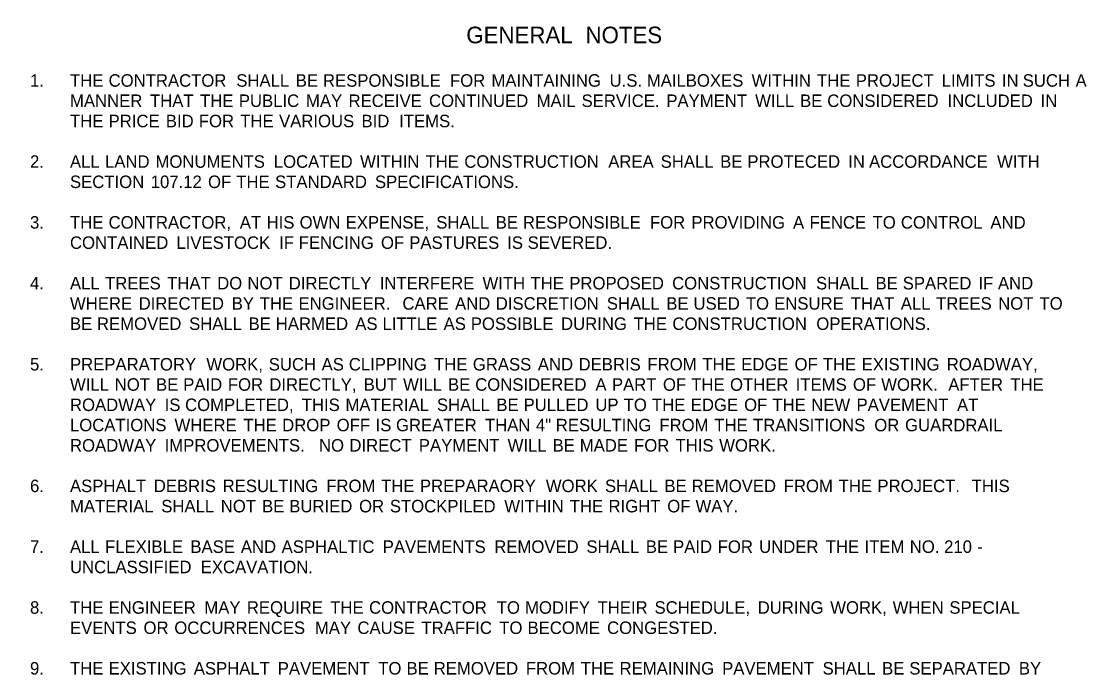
# Model space of a CAD drawing. Extents: x 1930579 to 1932218, y 596452 to 599480.
# Drawn here: x 1930760 to 1931323, y 599048 to 599394 of the extents above; entities that cross this region are included whole.
import ezdxf

# ---------------------------------------------------------------- set-up
doc = ezdxf.new("R2010")
doc.units = 0
doc.layers.add('Default', color=7, linetype='Continuous')
doc.layers.add('R_Border', color=7, linetype='Continuous')

msp = doc.modelspace()

# ---------------------------------------------------------------- linework, layer by layer
at = {"layer": 'R_Border'}
msp.add_line((1930759.59, 599393.53), (1930759.59, 599393.53), dxfattribs=at)

# ---------------------------------------------------------------- texts
at = {"layer": 'Default'}
for s, height, p in [('GENERAL', 8.8, (1930994.83, 599381.89)), (' NOTES', 8.8, (1931054.58, 599381.89)), ('1.', 6.6, (1930764.2, 599358.92)), ('THE', 6.6, (1930785.33, 599358.92)), (' CONTRACTOR', 6.6, (1930803.29, 599358.92)), (' SHALL', 6.6, (1930870.79, 599358.92)), (' BE', 6.6, (1930902.24, 599358.92)), (' RESPONSIBLE', 6.6, (1930916.61, 599358.92)), (' FOR', 6.6, (1930983.78, 599358.92)), (' MAINTAINING', 6.6, (1931005.68, 599358.92)), (' U.S.', 6.6, (1931068.12, 599358.92)), (' MAILBOXES', 6.6, (1931087.81, 599358.92)), (' WITHIN', 6.6, (1931143.19, 599358.92)), (' THE', 6.6, (1931177.77, 599358.92)), (' PROJECT', 6.6, (1931198.29, 599358.92)), (' LIMITS', 6.6, (1931243.71, 599358.92)), (' IN', 6.6, (1931275.5, 599358.92)), (' SUCH', 6.6, (1931286.53, 599358.92)), (' A', 6.6, (1931314.47, 599358.92)), ('MANNER', 6.6, (1930785.33, 599348.2)), (' THAT', 6.6, (1930825.17, 599348.2)), (' THE', 6.6, (1930851.63, 599348.2)), (' PUBLIC', 6.6, (1930872.14, 599348.2)), (' MAY', 6.6, (1930907.65, 599348.2)), (' RECEIVE', 6.6, (1930930.13, 599348.2)), (' CONTINUED', 6.6, (1930972.68, 599348.2)), (' MAIL', 6.6, (1931029.57, 599348.2)), (' SERVICE.', 6.6, (1931053.33, 599348.2)), (' PAYMENT', 6.6, (1931098.13, 599348.2)), (' WILL', 6.6, (1931145.09, 599348.2)), (' BE', 6.6, (1931168.84, 599348.2)), (' CONSIDERED', 6.6, (1931183.21, 599348.2)), (' INCLUDED', 6.6, (1931246.77, 599348.2)), (' IN', 6.6, (1931295.98, 599348.2)), ('THE', 6.6, (1930785.33, 599337.47)), (' PRICE', 6.6, (1930803.29, 599337.47)), (' BID', 6.6, (1930833.54, 599337.47)), (' FOR', 6.6, (1930850.98, 599337.47)), (' THE', 6.6, (1930872.88, 599337.47)), (' VARIOUS', 6.6, (1930893.4, 599337.47)), (' BID', 6.6, (1930936.99, 599337.47)), ('  ITEMS.', 6.6, (1930954.43, 599337.47)), ('2.', 6.6, (1930764.2, 599316.02)), ('ALL', 6.6, (1930785.33, 599316.02)), (' LAND', 6.6, (1930801.41, 599316.02)), (' MONUMENTS', 6.6, (1930828.08, 599316.02)), (' LOCATED', 6.6, (1930890.61, 599316.02)), (' WITHIN', 6.6, (1930936.24, 599316.02)), (' THE', 6.6, (1930970.82, 599316.02)), (' CONSTRUCTION', 6.6, (1930991.34, 599316.02)), (' AREA', 6.6, (1931067.43, 599316.02)), (' SHALL', 6.6, (1931095.13, 599316.02)), (' BE', 6.6, (1931126.58, 599316.02)), (' PROTECED', 6.6, (1931140.95, 599316.02)), (' IN', 6.6, (1931194.26, 599316.02)), (' ACCORDANCE', 6.6, (1931205.29, 599316.02)), (' WITH', 6.6, (1931272.95, 599316.02)), ('SECTION', 6.6, (1930785.33, 599305.3)), (' 107.12', 6.6, (1930825.57, 599305.3)), (' OF', 6.6, (1930855.84, 599305.3)), (' THE', 6.6, (1930870.78, 599305.3)), (' STANDARD', 6.6, (1930891.3, 599305.3)), (' SPECIFICATIONS.', 6.6, (1930944.1, 599305.3)), ('3.', 6.6, (1930764.2, 599283.85)), ('THE', 6.6, (1930785.33, 599283.85)), (' CONTRACTOR,', 6.6, (1930803.29, 599283.85)), (' AT', 6.6, (1930872.66, 599283.85)), (' HIS', 6.6, (1930886.82, 599283.85)), (' OWN', 6.6, (1930904.27, 599283.85)), (' EXPENSE,', 6.6, (1930928.61, 599283.85)), (' SHALL', 6.6, (1930976.49, 599283.85)), (' BE', 6.6, (1931007.94, 599283.85)), (' RESPONSIBLE', 6.6, (1931022.31, 599283.85)), (' FOR', 6.6, (1931089.47, 599283.85)), (' PROVIDING', 6.6, (1931111.37, 599283.85)), (' A', 6.6, (1931165.11, 599283.85)), (' FENCE', 6.6, (1931173.84, 599283.85)), (' TO', 6.6, (1931207.16, 599283.85)), (' CONTROL', 6.6, (1931222.12, 599283.85)), (' AND', 6.6, (1931269.44, 599283.85)), ('CONTAINED', 6.6, (1930785.33, 599273.12)), (' LIVESTOCK', 6.6, (1930839.15, 599273.12)), (' IF', 6.6, (1930893.46, 599273.12)), (' FENCING', 6.6, (1930903.79, 599273.12)), (' OF', 6.6, (1930947.27, 599273.12)), (' PASTURES', 6.6, (1930962.22, 599273.12)), (' IS', 6.6, (1931014.01, 599273.12)), (' SEVERED.', 6.6, (1931024.8, 599273.12)), ('4.', 6.6, (1930764.2, 599251.67)), ('ALL', 6.6, (1930785.33, 599251.67)), (' TREES', 6.6, (1930801.41, 599251.67)), (' THAT', 6.6, (1930834.24, 599251.67)), (' DO', 6.6, (1930860.69, 599251.67)), (' NOT', 6.6, (1930876.68, 599251.67)), (' DIRECTLY', 6.6, (1930898.52, 599251.67)), (' INTERFERE', 6.6, (1930946.62, 599251.67)), (' WITH', 6.6, (1931000.95, 599251.67)), (' THE', 6.6, (1931026.32, 599251.67)), (' PROPOSED', 6.6, (1931046.84, 599251.67)), (' CONSTRUCTION', 6.6, (1931101.18, 599251.67)), (' SHALL', 6.6, (1931177.28, 599251.67)), (' BE', 6.6, (1931208.73, 599251.67)), (' SPARED', 6.6, (1931223.1, 599251.67)), (' IF', 6.6, (1931263.1, 599251.67)), (' AND', 6.6, (1931273.43, 599251.67)), ('WHERE', 6.6, (1930785.33, 599240.95)), (' DIRECTED', 6.6, (1930819.17, 599240.95)), (' BY', 6.6, (1930868.38, 599240.95)), (' THE', 6.6, (1930883.17, 599240.95)), (' ENGINEER.', 6.6, (1930903.69, 599240.95)), ('  CARE', 6.6, (1930956.17, 599240.95)), (' AND', 6.6, (1930986.43, 599240.95)), (' DISCRETION', 6.6, (1931007.97, 599240.95)), (' SHALL', 6.6, (1931066.65, 599240.95)), (' BE', 6.6, (1931098.1, 599240.95)), (' USED', 6.6, (1931112.47, 599240.95)), (' TO', 6.6, (1931140.16, 599240.95)), (' ENSURE', 6.6, (1931155.12, 599240.95)), (' THAT', 6.6, (1931195.62, 599240.95)), (' ALL', 6.6, (1931222.08, 599240.95)), (' TREES', 6.6, (1931240.72, 599240.95)), (' NOT', 6.6, (1931273.55, 599240.95)), (' TO', 6.6, (1931295.39, 599240.95)), ('BE', 6.6, (1930785.33, 599230.22)), (' REMOVED', 6.6, (1930797.14, 599230.22)), (' SHALL', 6.6, (1930845.84, 599230.22)), (' BE', 6.6, (1930877.3, 599230.22)), (' HARMED', 6.6, (1930891.67, 599230.22)), (' AS', 6.6, (1930933.7, 599230.22)), (' LITTLE', 6.6, (1930948.08, 599230.22)), (' AS', 6.6, (1930980.39, 599230.22)), (' POSSIBLE', 6.6, (1930994.77, 599230.22)), (' DURING', 6.6, (1931042.46, 599230.22)), (' THE', 6.6, (1931080.81, 599230.22)), (' CONSTRUCTION', 6.6, (1931101.33, 599230.22)), (' OPERATIONS.', 6.6, (1931177.42, 599230.22)), ('5.', 6.6, (1930764.2, 599208.77)), ('PREPARATORY', 6.6, (1930785.33, 599208.77)), (' WORK,', 6.6, (1930854.97, 599208.77)), (' SUCH', 6.6, (1930887.96, 599208.77)), (' AS', 6.6, (1930915.9, 599208.77)), (' CLIPPING', 6.6, (1930930.29, 599208.77)), (' THE', 6.6, (1930975.31, 599208.77)), (' GRASS', 6.6, (1930995.83, 599208.77)), (' AND', 6.6, (1931030.2, 599208.77)), (' DEBRIS', 6.6, (1931051.74, 599208.77)), (' FROM', 6.6, (1931088.15, 599208.77)), (' THE', 6.6, (1931117.17, 599208.77)), (' EDGE', 6.6, (1931137.68, 599208.77)), (' OF', 6.6, (1931165.89, 599208.77)), (' THE', 6.6, (1931180.84, 599208.77)), (' EXISTING', 6.6, (1931201.35, 599208.77)), (' ROADWAY,', 6.6, (1931246.38, 599208.77)), ('WILL', 6.6, (1930785.33, 599198.05)), (' NOT', 6.6, (1930806.52, 599198.05)), (' BE', 6.6, (1930828.36, 599198.05)), (' PAID', 6.6, (1930842.74, 599198.05)), (' FOR', 6.6, (1930866.33, 599198.05)), (' DIRECTLY,', 6.6, (1930888.23, 599198.05)), (' BUT', 6.6, (1930938.14, 599198.05)), (' WILL', 6.6, (1930958.96, 599198.05)), (' BE', 6.6, (1930982.71, 599198.05)), (' CONSIDERED', 6.6, (1930997.08, 599198.05)), (' A', 6.6, (1931060.64, 599198.05)), (' PART', 6.6, (1931069.37, 599198.05)), (' OF', 6.6, (1931096.34, 599198.05)), (' THE', 6.6, (1931111.29, 599198.05)), (' OTHER', 6.6, (1931131.8, 599198.05)), (' ITEMS', 6.6, (1931166.52, 599198.05)), (' OF', 6.6, (1931196.78, 599198.05)), (' WORK.', 6.6, (1931211.72, 599198.05)), ('  AFTER', 6.6, (1931244.73, 599198.05)), (' THE', 6.6, (1931279.96, 599198.05)), ('ROADWAY', 6.6, (1930785.33, 599187.32)), (' IS', 6.6, (1930832.92, 599187.32)), (' COMPLETED,', 6.6, (1930843.71, 599187.32)), (' THIS', 6.6, (1930905.4, 599187.32)), (' MATERIAL', 6.6, (1930928.49, 599187.32)), (' SHALL', 6.6, (1930976.84, 599187.32)), (' BE', 6.6, (1931008.29, 599187.32)), (' PULLED', 6.6, (1931022.66, 599187.32)), (' UP', 6.6, (1931060.61, 599187.32)), (' TO', 6.6, (1931075.58, 599187.32)), (' THE', 6.6, (1931090.53, 599187.32)), (' EDGE', 6.6, (1931111.05, 599187.32)), (' OF', 6.6, (1931139.25, 599187.32)), (' THE', 6.6, (1931154.2, 599187.32)), (' NEW', 6.6, (1931174.71, 599187.32)), (' PAVEMENT', 6.6, (1931198.68, 599187.32)), (' AT', 6.6, (1931251.8, 599187.32)), ('LOCATIONS', 6.6, (1930785.33, 599176.6)), (' WHERE', 6.6, (1930838.14, 599176.6)), (' THE', 6.6, (1930874.54, 599176.6)), (' DROP', 6.6, (1930895.05, 599176.6)), (' OFF', 6.6, (1930923.86, 599176.6)), (' IS', 6.6, (1930944.44, 599176.6)), (' GREATER', 6.6, (1930955.23, 599176.6)), (' THAN', 6.6, (1931002.25, 599176.6)), (' 4"', 6.6, (1931029.16, 599176.6)), (' RESULTING', 6.6, (1931039.69, 599176.6)), (' FROM', 6.6, (1931094.45, 599176.6)), (' THE', 6.6, (1931123.47, 599176.6)), (' TRANSITIONS', 6.6, (1931143.98, 599176.6)), (' OR', 6.6, (1931208.06, 599176.6)), (' GUARDRAIL', 6.6, (1931224.33, 599176.6)), ('ROADWAY', 6.6, (1930785.33, 599165.87)), (' IMPROVEMENTS.', 6.6, (1930832.92, 599165.87)), ('  NO', 6.6, (1930912.05, 599165.87)), (' DIRECT', 6.6, (1930930.59, 599165.87)), (' PAYMENT', 6.6, (1930967.29, 599165.87)), (' WILL', 6.6, (1931014.25, 599165.87)), (' BE', 6.6, (1931038, 599165.87)), (' MADE', 6.6, (1931052.37, 599165.87)), (' FOR', 6.6, (1931081.09, 599165.87)), (' THIS', 6.6, (1931102.99, 599165.87)), (' WORK.', 6.6, (1931126.07, 599165.87)), ('6.', 6.6, (1930764.2, 599144.42)), ('ASPHALT', 6.6, (1930785.33, 599144.42)), (' DEBRIS', 6.6, (1930827.18, 599144.42)), (' RESULTING', 6.6, (1930863.59, 599144.42)), (' FROM', 6.6, (1930918.35, 599144.42)), (' THE', 6.6, (1930947.37, 599144.42)), (' PREPARAORY', 6.6, (1930967.88, 599144.42)), (' WORK', 6.6, (1931034.44, 599144.42)), (' SHALL', 6.6, (1931065.67, 599144.42)), (' BE', 6.6, (1931097.12, 599144.42)), (' REMOVED', 6.6, (1931111.49, 599144.42)), (' FROM', 6.6, (1931160.19, 599144.42)), (' THE', 6.6, (1931189.21, 599144.42)), (' PROJECT.', 6.6, (1931209.73, 599144.42)), ('  THIS', 6.6, (1931257.09, 599144.42)), ('MATERIAL', 6.6, (1930785.33, 599133.7)), (' SHALL', 6.6, (1930831.13, 599133.7)), (' NOT', 6.6, (1930862.58, 599133.7)), (' BE', 6.6, (1930884.42, 599133.7)), (' BURIED', 6.6, (1930898.79, 599133.7)), (' OR', 6.6, (1930935.7, 599133.7)), (' STOCKPILED', 6.6, (1930951.97, 599133.7)), (' WITHIN', 6.6, (1931012.46, 599133.7)), (' THE', 6.6, (1931047.05, 599133.7)), (' RIGHT', 6.6, (1931067.56, 599133.7)), (' OF', 6.6, (1931098.63, 599133.7)), (' WAY.', 6.6, (1931113.57, 599133.7)), (' BASE', 6.6, (1930846.53, 599112.25)), (' ASPHALTIC', 6.6, (1930894.75, 599112.25)), (' PAVEMENTS', 6.6, (1930948.2, 599112.25)), (' REMOVED', 6.6, (1931007.16, 599112.25)), (' SHALL', 6.6, (1931055.86, 599112.25)), (' FOR', 6.6, (1931125.28, 599112.25)), (' NO.', 6.6, (1931226.82, 599112.25)), (' 210', 6.6, (1931244.97, 599112.25)), ('7.', 6.6, (1930764.2, 599112.25)), ('ALL', 6.6, (1930785.33, 599112.25)), (' FLEXIBLE', 6.6, (1930801.41, 599112.25)), (' AND', 6.6, (1930873.21, 599112.25)), (' BE', 6.6, (1931087.31, 599112.25)), (' PAID', 6.6, (1931101.69, 599112.25)), (' UNDER', 6.6, (1931147.18, 599112.25)), (' THE', 6.6, (1931182.41, 599112.25)), (' ITEM', 6.6, (1931202.92, 599112.25)), (' -', 6.6, (1931262.46, 599112.25)), ('UNCLASSIFIED', 6.6, (1930785.33, 599101.52)), (' EXCAVATION.', 6.6, (1930851.97, 599101.52)), ('8.', 6.6, (1930764.2, 599080.07)), ('THE', 6.6, (1930785.33, 599080.07)), (' ENGINEER', 6.6, (1930803.29, 599080.07)), (' MAY', 6.6, (1930853.89, 599080.07)), (' REQUIRE', 6.6, (1930876.37, 599080.07)), (' THE', 6.6, (1930920.46, 599080.07)), (' CONTRACTOR', 6.6, (1930940.97, 599080.07)), (' TO', 6.6, (1931008.48, 599080.07)), (' MODIFY', 6.6, (1931023.43, 599080.07)), (' THEIR', 6.6, (1931061.78, 599080.07)), (' SCHEDULE,', 6.6, (1931091.89, 599080.07)), (' DURING', 6.6, (1931146.41, 599080.07)), (' WORK,', 6.6, (1931184.77, 599080.07)), (' WHEN', 6.6, (1931217.76, 599080.07)), (' SPECIAL', 6.6, (1931247.74, 599080.07)), ('EVENTS', 6.6, (1930785.33, 599069.35)), (' OR', 6.6, (1930821.75, 599069.35)), (' OCCURRENCES', 6.6, (1930838.02, 599069.35)), (' MAY', 6.6, (1930912.35, 599069.35)), (' CAUSE', 6.6, (1930934.83, 599069.35)), (' TRAFFIC', 6.6, (1930968.67, 599069.35)), (' TO', 6.6, (1931009.8, 599069.35)), (' BECOME', 6.6, (1931024.76, 599069.35)), (' CONGESTED.', 6.6, (1931066.8, 599069.35)), ('9.', 6.6, (1930764.2, 599047.9)), ('THE', 6.6, (1930785.33, 599047.9)), (' EXISTING', 6.6, (1930803.29, 599047.9)), (' ASPHALT', 6.6, (1930848.31, 599047.9)), (' PAVEMENT', 6.6, (1930892.72, 599047.9)), (' TO', 6.6, (1930945.83, 599047.9)), (' BE', 6.6, (1930960.79, 599047.9)), (' REMOVED', 6.6, (1930975.16, 599047.9)), (' FROM', 6.6, (1931023.86, 599047.9)), (' THE', 6.6, (1931052.87, 599047.9)), (' REMAINING', 6.6, (1931073.39, 599047.9)), (' PAVEMENT', 6.6, (1931127.63, 599047.9)), (' SHALL', 6.6, (1931180.74, 599047.9)), (' BE', 6.6, (1931212.2, 599047.9)), (' SEPARATED', 6.6, (1931226.57, 599047.9)), (' BY', 6.6, (1931284.5, 599047.9))]:
    msp.add_text(s, height=height, dxfattribs=at).set_placement(p)

doc.saveas('drawing.dxf')
